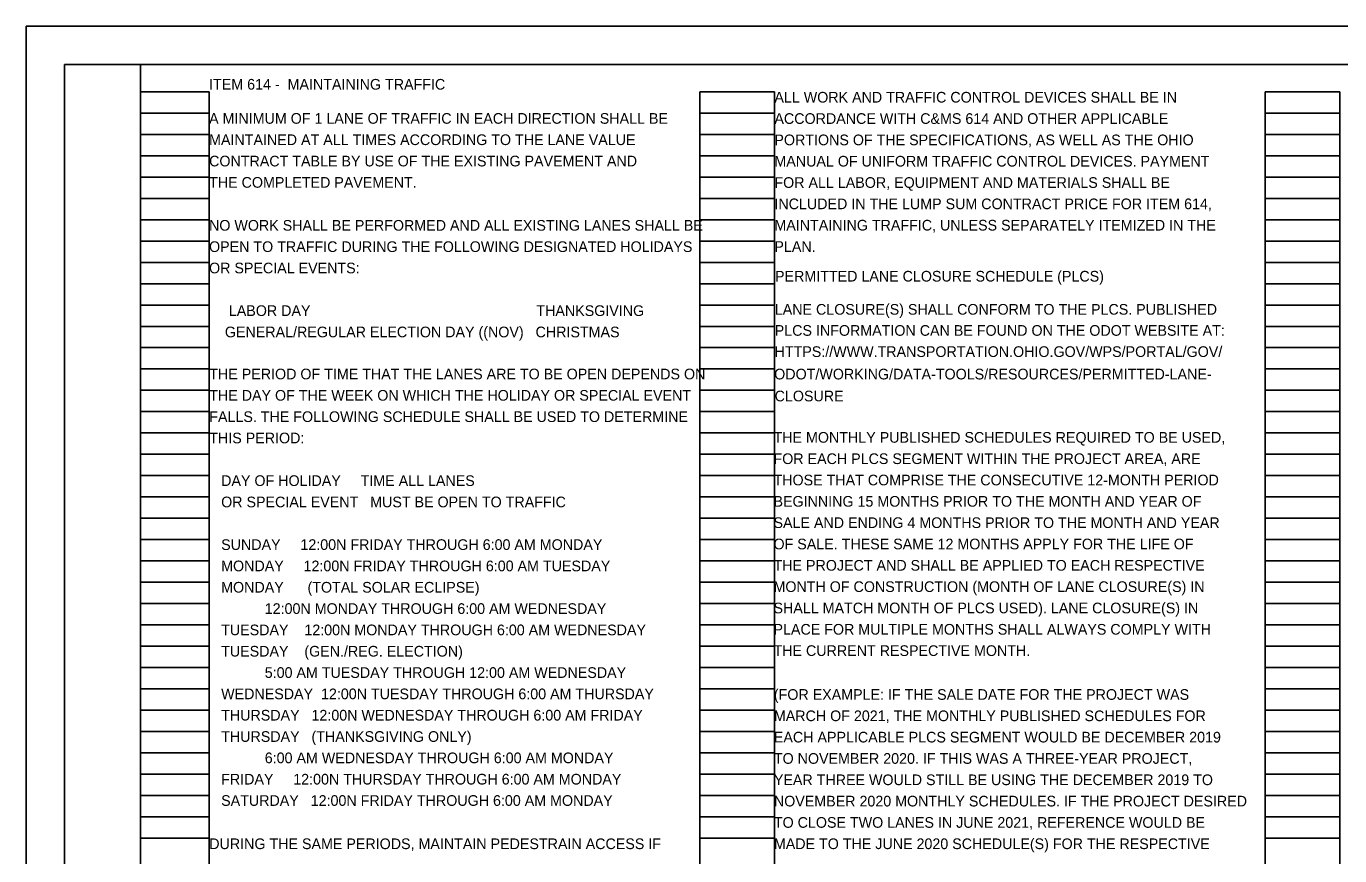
# Model space of a CAD drawing. Extents: x -40 to 107, y -47 to 37.
# Drawn here: x 0 to 17.24, y 11.11 to 22 of the extents above; entities that cross this region are included whole.
import ezdxf

# ---------------------------------------------------------------- set-up
doc = ezdxf.new("R2010")
doc.units = 0
for name, color, linetype in [('Default', 7, 'Continuous'), ('SH_Border', 7, 'Continuous'), ('SH_Cut_Line', 7, 'Continuous'), ('SH_Data', 7, 'Continuous'), ('SH_Text', 7, 'Continuous')]:
    doc.layers.add(name, color=color, linetype=linetype)

msp = doc.modelspace()

# ---------------------------------------------------------------- linework, layer by layer
at = {"layer": 'SH_Border'}
for points in [[(0.5, 21.5), (1.5, 21.5), (1.5, 0.5), (0.5, 0.5)], [(1.5, 21.5), (33.5, 21.5), (33.5, 0.5), (1.5, 0.5)]]:
    msp.add_lwpolyline(points, close=True, dxfattribs=at)
at = {"layer": 'SH_Cut_Line'}
msp.add_lwpolyline([(0, 0), (34, 0), (34, 22), (0, 22)], close=True, dxfattribs=at)
at = {"layer": 'SH_Data'}
for p, q in [((1.5, 0.98), (1.5, 21.14)), ((1.5, 21.14), (2.4, 21.14)), ((2.4, 0.98), (2.4, 21.14)), ((8.84, 0.98), (8.84, 21.14)), ((8.84, 21.14), (9.82, 21.14)), ((9.82, 0.98), (9.82, 21.14)), ((16.26, 0.98), (16.26, 21.14)), ((16.26, 21.14), (17.24, 21.14)), ((17.24, 0.98), (17.24, 21.14)), ((1.5, 20.86), (2.4, 20.86)), ((8.84, 20.86), (9.82, 20.86)), ((16.26, 20.86), (17.24, 20.86)), ((1.5, 20.58), (2.4, 20.58)), ((8.84, 20.58), (9.82, 20.58)), ((16.26, 20.58), (17.24, 20.58)), ((1.5, 20.3), (2.4, 20.3)), ((8.84, 20.3), (9.82, 20.3)), ((16.26, 20.3), (17.24, 20.3)), ((1.5, 20.02), (2.4, 20.02)), ((8.84, 20.02), (9.82, 20.02)), ((16.26, 20.02), (17.24, 20.02)), ((1.5, 19.74), (2.4, 19.74)), ((8.84, 19.74), (9.82, 19.74)), ((16.26, 19.74), (17.24, 19.74)), ((1.5, 19.46), (2.4, 19.46)), ((8.84, 19.46), (9.82, 19.46)), ((16.26, 19.46), (17.24, 19.46)), ((1.5, 19.18), (2.4, 19.18)), ((8.84, 19.18), (9.82, 19.18)), ((16.26, 19.18), (17.24, 19.18)), ((1.5, 18.9), (2.4, 18.9)), ((8.84, 18.9), (9.82, 18.9)), ((16.26, 18.9), (17.24, 18.9)), ((1.5, 18.62), (2.4, 18.62)), ((8.84, 18.62), (9.82, 18.62)), ((16.26, 18.62), (17.24, 18.62)), ((1.5, 18.34), (2.4, 18.34)), ((8.84, 18.34), (9.82, 18.34)), ((16.26, 18.34), (17.24, 18.34)), ((1.5, 18.06), (2.4, 18.06)), ((8.84, 18.06), (9.82, 18.06)), ((16.26, 18.06), (17.24, 18.06)), ((1.5, 17.78), (2.4, 17.78)), ((8.84, 17.78), (9.82, 17.78)), ((16.26, 17.78), (17.24, 17.78)), ((1.5, 17.5), (2.4, 17.5)), ((8.84, 17.5), (9.82, 17.5)), ((16.26, 17.5), (17.24, 17.5)), ((1.5, 17.22), (2.4, 17.22)), ((8.84, 17.22), (9.82, 17.22)), ((16.26, 17.22), (17.24, 17.22)), ((1.5, 16.94), (2.4, 16.94)), ((8.84, 16.94), (9.82, 16.94)), ((16.26, 16.94), (17.24, 16.94)), ((1.5, 16.66), (2.4, 16.66)), ((8.84, 16.66), (9.82, 16.66)), ((16.26, 16.66), (17.24, 16.66)), ((1.5, 16.38), (2.4, 16.38)), ((8.84, 16.38), (9.82, 16.38)), ((16.26, 16.38), (17.24, 16.38)), ((1.5, 16.1), (2.4, 16.1)), ((8.84, 16.1), (9.82, 16.1)), ((16.26, 16.1), (17.24, 16.1)), ((1.5, 15.82), (2.4, 15.82)), ((8.84, 15.82), (9.82, 15.82)), ((16.26, 15.82), (17.24, 15.82)), ((1.5, 15.54), (2.4, 15.54)), ((8.84, 15.54), (9.82, 15.54)), ((16.26, 15.54), (17.24, 15.54)), ((1.5, 15.26), (2.4, 15.26)), ((8.84, 15.26), (9.82, 15.26)), ((16.26, 15.26), (17.24, 15.26)), ((1.5, 14.98), (2.4, 14.98)), ((8.84, 14.98), (9.82, 14.98)), ((16.26, 14.98), (17.24, 14.98)), ((1.5, 14.7), (2.4, 14.7)), ((8.84, 14.7), (9.82, 14.7)), ((16.26, 14.7), (17.24, 14.7)), ((1.5, 14.42), (2.4, 14.42)), ((8.84, 14.42), (9.82, 14.42)), ((16.26, 14.42), (17.24, 14.42)), ((1.5, 14.14), (2.4, 14.14)), ((8.84, 14.14), (9.82, 14.14)), ((16.26, 14.14), (17.24, 14.14)), ((1.5, 13.86), (2.4, 13.86)), ((8.84, 13.86), (9.82, 13.86)), ((16.26, 13.86), (17.24, 13.86)), ((1.5, 13.58), (2.4, 13.58)), ((8.84, 13.58), (9.82, 13.58)), ((16.26, 13.58), (17.24, 13.58)), ((1.5, 13.3), (2.4, 13.3)), ((8.84, 13.3), (9.82, 13.3)), ((16.26, 13.3), (17.24, 13.3)), ((1.5, 13.02), (2.4, 13.02)), ((8.84, 13.02), (9.82, 13.02)), ((16.26, 13.02), (17.24, 13.02)), ((1.5, 12.74), (2.4, 12.74)), ((8.84, 12.74), (9.82, 12.74)), ((16.26, 12.74), (17.24, 12.74)), ((1.5, 12.46), (2.4, 12.46)), ((8.84, 12.46), (9.82, 12.46)), ((16.26, 12.46), (17.24, 12.46)), ((1.5, 12.18), (2.4, 12.18)), ((8.84, 12.18), (9.82, 12.18)), ((16.26, 12.18), (17.24, 12.18)), ((1.5, 11.9), (2.4, 11.9)), ((8.84, 11.9), (9.82, 11.9)), ((16.26, 11.9), (17.24, 11.9)), ((1.5, 11.62), (2.4, 11.62)), ((8.84, 11.62), (9.82, 11.62)), ((16.26, 11.62), (17.24, 11.62)), ((1.5, 11.34), (2.4, 11.34)), ((8.84, 11.34), (9.82, 11.34)), ((16.26, 11.34), (17.24, 11.34))]:
    msp.add_line(p, q, dxfattribs=at)

# ---------------------------------------------------------------- texts
at = {"layer": 'Default'}
for s, p in [('PERMITTED LANE CLOSURE SCHEDULE (PLCS)', (9.828, 18.648)), ('PLCS INFORMATION CAN BE FOUND ON THE ODOT WEBSITE AT:', (9.824, 17.936)), ('HTTPS://WWW.TRANSPORTATION.OHIO.GOV/WPS/PORTAL/GOV/', (9.822, 17.658)), ('ODOT/WORKING/DATA-TOOLS/RESOURCES/PERMITTED-LANE-', (9.817, 17.363)), ('CLOSURE', (9.823, 17.075)), ('THE MONTHLY PUBLISHED SCHEDULES REQUIRED TO BE USED,', (9.808, 16.532)), ('FOR EACH PLCS SEGMENT WITHIN THE PROJECT AREA, ARE', (9.808, 16.252)), ('THOSE THAT COMPRISE THE CONSECUTIVE 12-MONTH PERIOD', (9.808, 15.972)), ('BEGINNING 15 MONTHS PRIOR TO THE MONTH AND YEAR OF', (9.808, 15.692)), ('SALE AND ENDING 4 MONTHS PRIOR TO THE MONTH AND YEAR', (9.808, 15.412)), ('OF SALE. THESE SAME 12 MONTHS APPLY FOR THE LIFE OF', (9.808, 15.132)), ('THE PROJECT AND SHALL BE APPLIED TO EACH RESPECTIVE', (9.808, 14.852)), ('MONTH OF CONSTRUCTION (MONTH OF LANE CLOSURE(S) IN', (9.808, 14.572)), ('SHALL MATCH MONTH OF PLCS USED). LANE CLOSURE(S) IN', (9.808, 14.292)), ('PLACE FOR MULTIPLE MONTHS SHALL ALWAYS COMPLY WITH ', (9.808, 14.012)), ('THE CURRENT RESPECTIVE MONTH.', (9.808, 13.732)), ('(FOR EXAMPLE: IF THE SALE DATE FOR THE PROJECT WAS', (9.813, 13.156)), ('MARCH OF 2021, THE MONTHLY PUBLISHED SCHEDULES FOR', (9.813, 12.876)), ('EACH APPLICABLE PLCS SEGMENT WOULD BE DECEMBER 2019', (9.813, 12.596)), ('TO NOVEMBER 2020. IF THIS WAS A THREE-YEAR PROJECT,', (9.813, 12.316)), ('YEAR THREE WOULD STILL BE USING THE DECEMBER 2019 TO', (9.813, 12.036)), ('NOVEMBER 2020 MONTHLY SCHEDULES. IF THE PROJECT DESIRED', (9.813, 11.756)), ('TO CLOSE TWO LANES IN JUNE 2021, REFERENCE WOULD BE', (9.813, 11.476)), ('MADE TO THE JUNE 2020 SCHEDULE(S) FOR THE RESPECTIVE', (9.813, 11.196))]:
    msp.add_text(s, height=0.14, dxfattribs=at).set_placement(p)
at = {"layer": 'SH_Text'}
for s, p in [('ITEM 614 -  MAINTAINING TRAFFIC', (2.4, 21.168)), ('ALL WORK AND TRAFFIC CONTROL DEVICES SHALL BE IN', (9.82, 20.998)), ('A MINIMUM OF 1 LANE OF TRAFFIC IN EACH DIRECTION SHALL BE', (2.4, 20.72)), ('ACCORDANCE WITH C&MS 614 AND OTHER APPLICABLE', (9.82, 20.718)), ('MAINTAINED AT ALL TIMES ACCORDING TO THE LANE VALUE ', (2.4, 20.44)), ('PORTIONS OF THE SPECIFICATIONS, AS WELL AS THE OHIO', (9.82, 20.438)), ('CONTRACT TABLE BY USE OF THE EXISTING PAVEMENT AND', (2.4, 20.16)), ('MANUAL OF UNIFORM TRAFFIC CONTROL DEVICES. PAYMENT', (9.82, 20.158)), ('THE COMPLETED PAVEMENT.', (2.4, 19.88)), ('FOR ALL LABOR, EQUIPMENT AND MATERIALS SHALL BE', (9.82, 19.878)), ('INCLUDED IN THE LUMP SUM CONTRACT PRICE FOR ITEM 614,', (9.82, 19.598)), ('NO WORK SHALL BE PERFORMED AND ALL EXISTING LANES SHALL BE', (2.399, 19.316)), ('MAINTAINING TRAFFIC, UNLESS SEPARATELY ITEMIZED IN THE', (9.82, 19.318)), ('OPEN TO TRAFFIC DURING THE FOLLOWING DESIGNATED HOLIDAYS', (2.399, 19.036)), ('PLAN.', (9.82, 19.038)), ('OR SPECIAL EVENTS:', (2.399, 18.756)), ('     LABOR DAY                                                         THANKSGIVING', (2.399, 18.196)), ('LANE CLOSURE(S) SHALL CONFORM TO THE PLCS. PUBLISHED', (9.825, 18.213)), ('    GENERAL/REGULAR ELECTION DAY ((NOV)   CHRISTMAS', (2.399, 17.916)), ('THE PERIOD OF TIME THAT THE LANES ARE TO BE OPEN DEPENDS ON', (2.402, 17.364)), ('THE DAY OF THE WEEK ON WHICH THE HOLIDAY OR SPECIAL EVENT', (2.402, 17.084)), ('FALLS. THE FOLLOWING SCHEDULE SHALL BE USED TO DETERMINE', (2.402, 16.804)), ('THIS PERIOD:', (2.402, 16.524)), ('   DAY OF HOLIDAY     TIME ALL LANES', (2.402, 15.964)), ('   OR SPECIAL EVENT   MUST BE OPEN TO TRAFFIC', (2.402, 15.684)), ('   SUNDAY     12:00N FRIDAY THROUGH 6:00 AM MONDAY', (2.402, 15.124)), ('   MONDAY     12:00N FRIDAY THROUGH 6:00 AM TUESDAY', (2.402, 14.844)), ('   MONDAY      (TOTAL SOLAR ECLIPSE)', (2.402, 14.564)), ('              12:00N MONDAY THROUGH 6:00 AM WEDNESDAY', (2.402, 14.284)), ('   TUESDAY    12:00N MONDAY THROUGH 6:00 AM WEDNESDAY', (2.402, 14.004)), ('   TUESDAY    (GEN./REG. ELECTION)', (2.402, 13.724)), ('              5:00 AM TUESDAY THROUGH 12:00 AM WEDNESDAY', (2.402, 13.444)), ('   WEDNESDAY  12:00N TUESDAY THROUGH 6:00 AM THURSDAY', (2.402, 13.164)), ('   THURSDAY   12:00N WEDNESDAY THROUGH 6:00 AM FRIDAY', (2.402, 12.884)), ('   THURSDAY   (THANKSGIVING ONLY)', (2.402, 12.604)), ('              6:00 AM WEDNESDAY THROUGH 6:00 AM MONDAY', (2.402, 12.324)), ('   FRIDAY     12:00N THURSDAY THROUGH 6:00 AM MONDAY', (2.402, 12.044)), ('   SATURDAY   12:00N FRIDAY THROUGH 6:00 AM MONDAY', (2.402, 11.764)), ('DURING THE SAME PERIODS, MAINTAIN PEDESTRAIN ACCESS IF', (2.402, 11.196))]:
    msp.add_text(s, height=0.14, dxfattribs=at).set_placement(p)

doc.saveas('drawing.dxf')
